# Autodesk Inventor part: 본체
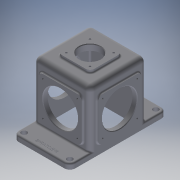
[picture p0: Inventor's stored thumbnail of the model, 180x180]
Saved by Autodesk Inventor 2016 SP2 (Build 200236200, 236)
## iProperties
Created: 2018-09
Part Number: 본체
Material: 알루미늄 6061
Document SubType Name: Modeling
Designer: mduedu
Density: 2.71 g/cm^3
Mass: 973.075 g
Surface Area: 1113.23 cm^2
Volume: 359.068 cm^3
Appearance: 기본값
Author: mduedu
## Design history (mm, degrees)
sketch "스케치1"
  geometry: L1 (90, 52.5)-(-90, 52.5); L2 (-90, 52.5)-(-90, -52.5); L3 (-90, -52.5)-(90, -52.5); L4 (90, -52.5)-(90, 52.5); L5 (90, 52.5)-(-90, -52.5); L6 (-90, 52.5)-(90, -52.5); 1 further point
  constraints: 12 end point, 2 midpoint, 2 parallel, 1 horizontal, 1 perpendicular
  dimensions: "d0" = 180 distance of L3.end L2.end; "d1" = 105 distance of L2.end L1.end
extrude "돌출1" new body sketch "스케치1" distance "d2" = 10; taper "d3" = 0 deg
sketch "스케치2"
  geometry: L1 (-52.5, -52.5)-(52.5, -52.5); L2 (52.5, -52.5)-(52.5, 52.5); L3 (52.5, 52.5)-(-52.5, 52.5); L4 (-52.5, 52.5)-(-52.5, -52.5); L5 (-52.5, -52.5)-(52.5, 52.5); L6 (52.5, -52.5)-(-52.5, 52.5); 1 further point
  constraints: 12 end point, 2 midpoint, 2 parallel, 1 horizontal, 1 perpendicular
  dimensions: "d4" = 105 distance of L3.end L2.end; "d5" = 105 distance of L2.end L1.end
extrude "돌출2" join sketch "스케치2" distance "d6" = 105; taper "d7" = 0 deg
node "작업 평면1"
sketch "스케치3"
  geometry: L1 (-52.5, 52.5)-(52.5, 52.5) reference; L2 (52.5, 52.5)-(52.5, -52.5) reference; L3 (52.5, -52.5)-(-52.5, -52.5) reference; L4 (-52.5, -52.5)-(-52.5, 52.5) reference; L5 (46.5, 46.5)-(-46.5, 46.5); L6 (-46.5, 46.5)-(-46.5, -46.5); L7 (-46.5, -46.5)-(46.5, -46.5); L8 (46.5, -46.5)-(46.5, 46.5); 1 further point
  constraints: 8 end point, 3 other
  dimensions: "d9" = 6 distance between parallel lines of L5 L1
extrude "돌출3" cut sketch "스케치3" stored distance "d10" = 105; taper "d11" = 0 deg
fillet "모깎기1" dims "d12" = 9
fillet "모깎기2" dims "d13" = 9
fillet "모깎기3" dims "d14" = 3
fillet "모깎기4" dims "d15" = 3
sketch "스케치4"
  geometry: L1 (-30, -30)-(30, -30); L2 (30, -30)-(30, 30); L3 (30, 30)-(-30, 30); L4 (-30, 30)-(-30, -30); L5 (-30, -30)-(30, 30); L6 (30, -30)-(-30, 30); 1 further point
  constraints: 12 end point, 2 midpoint, 2 parallel, 1 horizontal, 1 perpendicular
  dimensions: "d16" = 60 distance of L3.end L2.end; "d17" = 60 distance of L2.end L1.end
extrude "돌출4" join sketch "스케치4" distance "d18" = 5; taper "d19" = 0 deg
fillet "모깎기5" dims "d20" = 8
fillet "모깎기6" dims "d21" = 3
sketch "스케치5"
  geometry: C1 r 20 at (0, 0); 1 further point
  constraints: 1 centre point, 1 coincident
  dimensions: "d22" = 40 diameter of C1
extrude "돌출5" cut sketch "스케치5" stored distance "d23" = 5; taper "d24" = 0 deg
sketch "스케치6"
  geometry: L1 (50, 17.5)-(130, 17.5); L2 (130, 17.5)-(130, 97.5); L3 (130, 97.5)-(50, 97.5); L4 (50, 97.5)-(50, 17.5); L5 (50, 17.5)-(130, 97.5); L6 (130, 17.5)-(50, 97.5); L7 (0, 0)-(180, 0) reference; 4 further points
  constraints: 12 end point, 4 midpoint, 2 parallel, 1 horizontal, 1 perpendicular, 1 vertical alignment
  dimensions: "d25" = 80 distance of L3.end L2.end; "d26" = 80 distance of L2.end L1.end; "d27" = 57.5 distance of point (90, 0) point (90, 57.5)
extrude "돌출6" join sketch "스케치6" distance "d28" = 3; taper "d29" = 0 deg
fillet "모깎기7" dims "d30" = 8
sketch "스케치7"
  geometry: C1 r 32.5 at (90, 57.5); 1 further point
  constraints: 1 centre point, 1 vertical alignment
  dimensions: "d32" = 65 diameter of C1; "d33" = 57.5 distance of C1.centre point (90, 0)
extrude "돌출7" cut sketch "스케치7" stored distance "d34" = 3; taper "d35" = 0 deg
fillet "모깎기9" dims "d36" = 3
sketch "스케치8"
  geometry: L1 (3.5, 7.5)-(83.5, 7.5); L2 (83.5, 7.5)-(83.5, 87.5); L3 (83.5, 87.5)-(3.5, 87.5); L4 (3.5, 87.5)-(3.5, 7.5); L5 (3.5, 7.5)-(83.5, 87.5); L6 (83.5, 7.5)-(3.5, 87.5); L7 (-9, -10)-(96, -10) reference; C1 r 32.5 at (43.5, 47.5); 4 further points
  constraints: 12 end point, 4 midpoint, 2 parallel, 1 centre point, 1 coincident, 1 horizontal, 1 perpendicular, 1 vertical alignment
  dimensions: "d37" = 80 distance of L3.end L2.end; "d38" = 80 distance of L2.end L1.end; "d39" = 57.5 distance from line of point (43.5, 47.5) L7; "d40" = 65 diameter of C1
extrude "돌출8" join sketch "스케치8" distance "d41" = 3; taper "d42" = 0 deg
fillet "모깎기10" dims "d43" = 8
extrude "돌출9" cut sketch "스케치8" stored distance "d44" = 3; taper "d45" = 0 deg
fillet "모깎기11" dims "d46" = 3
sketch "스케치9"
  geometry: L1 (50, 89.5)-(50, 25.5) reference; L2 (58, 17.5)-(122, 17.5) reference; L3 (130, 25.5)-(130, 89.5) reference; L4 (122, 97.5)-(58, 97.5) reference; C1 r 32.5 at (90, 57.5) reference; A1 r 8 centre (58, 89.5) between (58, 97.5) and (50, 89.5) reference; A2 r 8 centre (58, 25.5) between (50, 25.5) and (58, 17.5) reference; A3 r 8 centre (122, 25.5) between (122, 17.5) and (130, 25.5) reference; A4 r 8 centre (122, 89.5) between (130, 89.5) and (122, 97.5) reference; 5 further points
  constraints: 4 coincident
hole "구멍1" sketch "스케치9" at (58, 89.5), (122, 89.5), (122, 25.5), (58, 25.5) diameter "d47" = 3.242; stored, may be unused: countersink angle "d51" = 90 deg, drill point angle "d53" = 118 deg; dims "d48" = 6, "d49" = 4, "d50" = 2, "d52" = 9
sketch "스케치10"
  geometry: L1 (11.5, 7.5)-(75.5, 7.5) reference; L2 (83.5, 15.5)-(83.5, 79.5) reference; L3 (75.5, 87.5)-(11.5, 87.5) reference; L4 (3.5, 79.5)-(3.5, 15.5) reference; C1 r 32.5 at (43.5, 47.5) reference; A1 r 8 centre (11.5, 15.5) between (3.5, 15.5) and (11.5, 7.5) reference; A2 r 8 centre (75.5, 15.5) between (75.5, 7.5) and (83.5, 15.5) reference; A3 r 8 centre (75.5, 79.5) between (83.5, 79.5) and (75.5, 87.5) reference; A4 r 8 centre (11.5, 79.5) between (11.5, 87.5) and (3.5, 79.5) reference; 5 further points
  constraints: 4 coincident
hole "구멍2" sketch "스케치10" at (11.5, 79.5), (75.5, 79.5), (75.5, 15.5), (11.5, 15.5) diameter "d54" = 3.242; stored, may be unused: countersink angle "d58" = 90 deg, drill point angle "d60" = 118 deg; dims "d55" = 6, "d56" = 4, "d57" = 2, "d59" = 9
sketch "스케치11"
  geometry: L1 (22, 30)-(-22, 30) reference; L2 (-30, 22)-(-30, -22) reference; L3 (-22, -30)-(22, -30) reference; L4 (30, -22)-(30, 22) reference; C1 r 20 at (0, 0) reference; A1 r 8 centre (22, 22) between (30, 22) and (22, 30) reference; A2 r 8 centre (-22, 22) between (-22, 30) and (-30, 22) reference; A3 r 8 centre (-22, -22) between (-30, -22) and (-22, -30) reference; A4 r 8 centre (22, -22) between (22, -30) and (30, -22) reference; 5 further points
  constraints: 4 coincident
hole "구멍3" sketch "스케치11" at (-22, 22), (22, 22), (22, -22), (-22, -22) diameter "d61" = 3.242; stored, may be unused: countersink angle "d65" = 90 deg, drill point angle "d67" = 118 deg; dims "d62" = 7, "d63" = 4, "d64" = 2, "d66" = 9
fillet "모깎기12" dims "d68" = 10
sketch "스케치12"
  geometry: L1 (-90, 42.5)-(-90, -42.5) reference; L2 (-80, -52.5)-(-43.5, -52.5) reference; L3 (-52.5, -43.5)-(-52.5, 43.5) reference; L4 (-43.5, 52.5)-(-80, 52.5) reference; A1 r 10 centre (-80, 42.5) between (-80, 52.5) and (-90, 42.5) reference; A2 r 10 centre (-80, -42.5) between (-90, -42.5) and (-80, -52.5) reference; A3 r 9 centre (-43.5, -43.5) between (-52.5, -43.5) and (-43.5, -52.5) reference; A4 r 9 centre (-43.5, 43.5) between (-43.5, 52.5) and (-52.5, 43.5) reference; 3 further points
  constraints: 2 coincident
hole "구멍4" sketch "스케치12" at (-80, 42.5), (-80, -42.5) diameter "d70" = 10; stored, may be unused: countersink angle "d74" = 90 deg, drill point angle "d76" = 118 deg; dims "d71" = 6, "d72" = 4, "d73" = 2, "d75" = 9
fillet "모깎기13" dims "d77" = 3
fillet "모깎기14" dims "d78" = 3
chamfer "모따기1" distance "d79" = 1; stored, may be unused: second distance "d80" = 2, angle "d81" = 45 deg
sketch "스케치13"
  geometry: L1 (90, -42.5)-(90, 42.5) reference; 2 further points
  constraints: 1 horizontal alignment, 1 other
  dimensions: "d82" = 10 distance from line of point (80, 0) L1
feature "엠보싱1" sketch "스케치13" dims "d83" = 0.5, "d84" = 0
node "솔리드1"
mirror "대칭1"
mirror "대칭2"
mirror "대칭3"
node "투영된 루프1"
node "투영된 루프2"
node "투영된 루프3"
node "투영된 루프4"
node "투영된 루프5"
other parameters: "d8" = -6
